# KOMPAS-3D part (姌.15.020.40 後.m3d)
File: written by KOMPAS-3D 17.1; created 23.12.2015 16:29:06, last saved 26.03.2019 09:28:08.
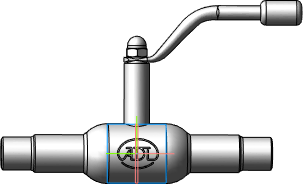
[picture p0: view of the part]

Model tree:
1. Операция без истории:4  (labels: Сталь 20  ГОСТ 1050-88)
